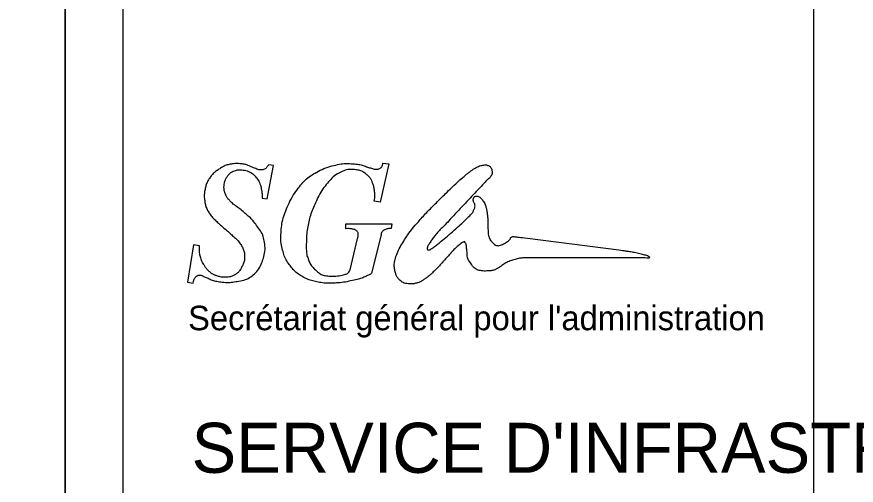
# Model space of a CAD drawing. Extents: x -21 to 21, y -29.7 to 0.
# Drawn here: x -0.42 to 6.85, y -12.39 to -8.34 of the extents above; entities that cross this region are included whole.
import ezdxf

# ---------------------------------------------------------------- set-up
doc = ezdxf.new("R2010")
doc.units = 0
doc.layers.add('Cartouches-Titres', color=7, linetype='Continuous')

msp = doc.modelspace()

# ---------------------------------------------------------------- linework, layer by layer
at = {"layer": 'Cartouches-Titres'}
for p, q in [((-0.0001, 0), (0, -29.7)), ((0, -29.7), (-0.0001, 0)), ((2.7347, -10.2257), (2.6519, -10.5569)), ((2.4658, -10.5273), (2.5308, -10.2578)), ((3.4574, -10.2822), (3.4561, -10.2822)), ((4.0037, -10.254), (4.7948, -10.3557)), ((4.7948, -10.4245), (4.0037, -10.4243))]:
    msp.add_line(p, q, dxfattribs=at)
for points in [[(-20.9999, -29.7), (0, -29.7), (0, 0), (-20.9999, 0)], [(-0.0001, 0), (0, -29.7), (21, -29.7), (20.9999, 0)], [(0, -29.7), (20.9999, -29.7), (20.9999, 0), (0, 0)]]:
    msp.add_lwpolyline(points, close=True, dxfattribs=at)
for points in [[(1.6644, -14.6077), (0.4999, -14.6077), (0.4999, -0.5036), (6.4782, -0.5036), (6.4783, -14.6077), (5.3139, -14.6077)], [(1.7061, -9.9067), (1.7482, -9.9131), (1.8017, -9.6236), (1.7635, -9.6179)], [(2.75, -9.6057), (2.801, -9.6108), (2.7258, -9.9433), (2.6748, -9.933)], [(2.4288, -10.1718), (2.4301, -10.1294), (2.8265, -10.1294), (2.8226, -10.1705)], [(1.1625, -10.3194), (1.1109, -10.313), (1.0593, -10.6358), (1.1084, -10.6429)]]:
    msp.add_lwpolyline(points, dxfattribs=at)
for points in [[(1.1084, -10.6429), (1.1083, -10.6301), (1.1121, -10.6154), (1.1186, -10.6044), (1.1251, -10.5932), (1.1361, -10.5816), (1.1473, -10.5761), (1.1556, -10.572), (1.1676, -10.5737), (1.1772, -10.5755), (1.1857, -10.5771), (1.1932, -10.5832), (1.2014, -10.5864), (1.2371, -10.6001), (1.2719, -10.6197), (1.3091, -10.6262), (1.359, -10.6349), (1.4129, -10.6395), (1.4627, -10.632), (1.5155, -10.6239), (1.5761, -10.6109), (1.6169, -10.5793), (1.6589, -10.5469), (1.6945, -10.4914), (1.7112, -10.44), (1.7287, -10.3864), (1.7318, -10.3192), (1.7195, -10.2642), (1.7082, -10.2133), (1.6726, -10.1652), (1.6405, -10.1223), (1.6127, -10.0852), (1.5748, -10.0552), (1.5398, -10.0241), (1.5045, -9.9928), (1.4626, -9.9682), (1.4296, -9.9349), (1.4109, -9.9162), (1.3937, -9.8927), (1.385, -9.8682), (1.3761, -9.8435), (1.3728, -9.8132), (1.3767, -9.7873), (1.3806, -9.7613), (1.3927, -9.733), (1.4085, -9.7122), (1.4222, -9.6943), (1.4441, -9.6788), (1.4653, -9.6711), (1.4885, -9.6627), (1.5169, -9.6613), (1.5417, -9.6641), (1.5642, -9.6666), (1.5874, -9.6761), (1.6074, -9.6872), (1.6235, -9.6962), (1.6382, -9.71), (1.6501, -9.7244), (1.6641, -9.7414), (1.6773, -9.7609), (1.6851, -9.7815), (1.6949, -9.8073), (1.6983, -9.8361), (1.703, -9.8637), (1.7053, -9.8778), (1.7064, -9.8924), (1.7061, -9.9067)], [(1.7635, -9.6179), (1.7598, -9.6216), (1.7562, -9.6255), (1.7527, -9.6294), (1.7455, -9.6375), (1.7407, -9.6494), (1.7316, -9.6538), (1.7184, -9.6603), (1.7008, -9.6635), (1.6857, -9.6622), (1.6672, -9.6605), (1.649, -9.6512), (1.6309, -9.6448), (1.604, -9.6353), (1.5785, -9.6188), (1.5506, -9.6147), (1.5109, -9.6087), (1.4675, -9.607), (1.4283, -9.6147), (1.394, -9.6213), (1.3596, -9.6383), (1.3302, -9.6577), (1.3014, -9.6766), (1.2737, -9.7016), (1.2537, -9.7295), (1.2344, -9.7564), (1.2193, -9.7896), (1.2123, -9.822), (1.2042, -9.8589), (1.2025, -9.9002), (1.2084, -9.9375), (1.2138, -9.9715), (1.2277, -10.0066), (1.246, -10.0357), (1.2668, -10.0686), (1.2974, -10.0961), (1.3257, -10.1236), (1.3601, -10.1571), (1.3994, -10.1854), (1.434, -10.2186), (1.4646, -10.2479), (1.4992, -10.276), (1.5213, -10.311), (1.5387, -10.3385), (1.5512, -10.374), (1.5526, -10.406), (1.5539, -10.4371), (1.5434, -10.4721), (1.5296, -10.5004), (1.5171, -10.526), (1.4966, -10.552), (1.4735, -10.5678), (1.452, -10.5824), (1.4222, -10.5899), (1.3958, -10.5915), (1.3663, -10.5933), (1.334, -10.5878), (1.3059, -10.578), (1.2828, -10.57), (1.2606, -10.5548), (1.2422, -10.5382), (1.2247, -10.5224), (1.2107, -10.5015), (1.1982, -10.4811), (1.1876, -10.4638), (1.1789, -10.4446), (1.1727, -10.4253), (1.167, -10.4074), (1.1644, -10.3882), (1.1625, -10.3694), (1.161, -10.3529), (1.161, -10.3359), (1.1625, -10.3194)], [(2.6519, -10.5569), (2.6476, -10.5623), (2.6416, -10.5669), (2.6353, -10.5697), (2.6013, -10.5845), (2.5668, -10.6005), (2.5308, -10.6095), (2.4712, -10.6244), (2.4097, -10.6372), (2.3485, -10.6416), (2.2954, -10.6454), (2.2401, -10.6435), (2.1879, -10.6339), (2.1428, -10.6255), (2.0963, -10.6103), (2.0566, -10.5877), (2.0182, -10.5658), (1.9809, -10.5351), (1.9534, -10.5004), (1.924, -10.4632), (1.8984, -10.4178), (1.8859, -10.372), (1.8703, -10.3151), (1.8646, -10.2515), (1.8693, -10.1923), (1.8744, -10.1282), (1.8904, -10.0618), (1.9152, -10.0023), (1.944, -9.933), (1.9835, -9.8645), (2.0299, -9.8059), (2.0655, -9.761), (2.1116, -9.72), (2.1612, -9.6917), (2.2217, -9.6571), (2.2917, -9.6314), (2.36, -9.6172), (2.4154, -9.6057), (2.4756, -9.6088), (2.532, -9.6147), (2.5707, -9.6187), (2.6076, -9.6365), (2.6455, -9.6468), (2.6598, -9.6506), (2.6744, -9.6568), (2.6888, -9.657), (2.7016, -9.6572), (2.716, -9.6539), (2.7271, -9.648), (2.7347, -9.644), (2.7407, -9.6352), (2.7449, -9.6275), (2.7483, -9.6211), (2.7503, -9.6129), (2.75, -9.6057)], [(2.6748, -9.933), (2.68, -9.9124), (2.6818, -9.89), (2.6799, -9.8688), (2.6771, -9.8374), (2.6721, -9.8043), (2.6608, -9.7751), (2.6517, -9.7517), (2.6377, -9.7268), (2.6187, -9.7109), (2.5931, -9.6895), (2.5596, -9.6681), (2.5269, -9.6634), (2.4844, -9.6574), (2.4321, -9.6604), (2.3931, -9.6788), (2.3433, -9.7024), (2.2966, -9.7454), (2.2606, -9.7892), (2.2188, -9.84), (2.1877, -9.9021), (2.1599, -9.9625), (2.1359, -10.0147), (2.1169, -10.0707), (2.1051, -10.1268), (2.0927, -10.1854), (2.0877, -10.2467), (2.0872, -10.3065), (2.0869, -10.3485), (2.0888, -10.3937), (2.1025, -10.4323), (2.1151, -10.4677), (2.1391, -10.5031), (2.1663, -10.5286), (2.1909, -10.5518), (2.2249, -10.5737), (2.258, -10.5787), (2.3107, -10.5866), (2.3723, -10.5798), (2.4237, -10.5671), (2.4416, -10.5627), (2.4603, -10.545), (2.4658, -10.5273)], [(3.4561, -10.2822), (3.4301, -10.2971), (3.4053, -10.3155), (3.3834, -10.3361), (3.3484, -10.369), (3.3182, -10.4073), (3.2853, -10.4426), (3.2545, -10.4757), (3.2248, -10.5102), (3.1923, -10.5415), (3.1687, -10.5641), (3.144, -10.5863), (3.1171, -10.6044), (3.0935, -10.6201), (3.0676, -10.6358), (3.0406, -10.6429), (3.0136, -10.6499), (2.9825, -10.651), (2.9552, -10.6467), (2.9362, -10.6437), (2.9155, -10.6342), (2.9017, -10.621), (2.8836, -10.6038), (2.8658, -10.5799), (2.8596, -10.5556), (2.8505, -10.52), (2.8466, -10.4773), (2.8558, -10.4413), (2.87, -10.3857), (2.8994, -10.3309), (2.9297, -10.2809), (2.9648, -10.2231), (3.0073, -10.1687), (3.0521, -10.1179), (3.1296, -10.0297), (3.2135, -9.9467), (3.2968, -9.8637), (3.344, -9.8166), (3.3936, -9.772), (3.4433, -9.7276), (3.4642, -9.7091), (3.4858, -9.6913), (3.5084, -9.675), (3.5279, -9.6609), (3.5479, -9.6463), (3.5695, -9.6365), (3.5874, -9.6284), (3.6076, -9.6232), (3.6269, -9.6211), (3.6394, -9.6197), (3.6539, -9.6213), (3.6651, -9.6262), (3.6743, -9.6303), (3.6831, -9.6392), (3.6881, -9.648), (3.6933, -9.6572), (3.6953, -9.6694), (3.6957, -9.6801), (3.6961, -9.6899), (3.6959, -9.7016), (3.6906, -9.7097), (3.6776, -9.7294), (3.6576, -9.7457), (3.6409, -9.7636), (3.5867, -9.8215), (3.5321, -9.879), (3.4778, -9.9369), (3.4199, -9.9984), (3.3623, -10.0601), (3.3044, -10.1217), (3.2726, -10.1556), (3.2385, -10.1875), (3.2088, -10.2231), (3.185, -10.2517), (3.164, -10.2831), (3.1438, -10.3143), (3.1394, -10.3211), (3.1365, -10.3294), (3.1349, -10.3374), (3.1339, -10.3423), (3.1336, -10.3497), (3.1362, -10.3528), (3.1383, -10.3553), (3.1447, -10.3538), (3.1489, -10.354), (3.1523, -10.3542), (3.1564, -10.3559), (3.1591, -10.354), (3.1903, -10.3328), (3.2214, -10.3092), (3.2509, -10.2847), (3.3102, -10.2356), (3.3686, -10.1852), (3.4255, -10.1333), (3.4604, -10.1014), (3.4948, -10.068), (3.5262, -10.0331), (3.5321, -10.0265), (3.5347, -10.0172), (3.5377, -10.0087), (3.5419, -9.9967), (3.5485, -9.9838), (3.5479, -9.9715), (3.5472, -9.9577), (3.5367, -9.9444), (3.5338, -9.9304), (3.5324, -9.9234), (3.5323, -9.9148), (3.5351, -9.9086), (3.5379, -9.9024), (3.5441, -9.8957), (3.5504, -9.8932), (3.5582, -9.8901), (3.5697, -9.8883), (3.5772, -9.8919), (3.5901, -9.8982), (3.6022, -9.9108), (3.6116, -9.9227), (3.6226, -9.9369), (3.6328, -9.9531), (3.6384, -9.9702), (3.6477, -9.9993), (3.6529, -10.0307), (3.6562, -10.0614), (3.6602, -10.0987), (3.6574, -10.1368), (3.66, -10.1743), (3.6616, -10.1967), (3.6621, -10.2202), (3.6689, -10.2411), (3.6748, -10.2591), (3.6854, -10.2775), (3.6983, -10.2911), (3.7096, -10.3032), (3.7261, -10.316), (3.7416, -10.3181), (3.758, -10.3203), (3.7777, -10.3115), (3.7938, -10.304), (3.8125, -10.2953), (3.8305, -10.2827), (3.8461, -10.2693), (3.8534, -10.263), (3.8552, -10.2498), (3.8627, -10.2449), (3.8696, -10.2404), (3.8805, -10.2401), (3.8894, -10.2411), (3.9275, -10.2451), (3.9656, -10.2494), (4.0037, -10.254)], [(2.5308, -10.2578), (2.5368, -10.2437), (2.5384, -10.2226), (2.5346, -10.2077), (2.532, -10.1978), (2.521, -10.1886), (2.5117, -10.1833), (2.5006, -10.177), (2.4864, -10.1749), (2.4734, -10.173), (2.4588, -10.171), (2.4435, -10.1706), (2.4288, -10.1718)], [(2.8226, -10.1705), (2.8109, -10.1694), (2.7982, -10.1708), (2.787, -10.1743), (2.7727, -10.1789), (2.7563, -10.1849), (2.7462, -10.1949), (2.7389, -10.202), (2.7339, -10.2155), (2.7347, -10.2257)], [(4.0037, -10.4243), (3.9872, -10.4245), (3.9708, -10.425), (3.9544, -10.4259), (3.9342, -10.4271), (3.9141, -10.4321), (3.8945, -10.4375), (3.8737, -10.4432), (3.8529, -10.4502), (3.8334, -10.4593), (3.8143, -10.4682), (3.7965, -10.4801), (3.7786, -10.4914), (3.7672, -10.4985), (3.757, -10.5077), (3.7454, -10.5145), (3.7353, -10.5205), (3.7247, -10.5265), (3.7136, -10.5299), (3.7005, -10.5338), (3.6865, -10.5355), (3.6728, -10.5363), (3.6499, -10.5377), (3.6263, -10.5398), (3.6039, -10.5363), (3.5855, -10.5334), (3.5654, -10.5278), (3.5504, -10.5171), (3.5331, -10.5047), (3.5195, -10.4851), (3.5071, -10.467), (3.4974, -10.453), (3.4885, -10.4372), (3.4841, -10.4208), (3.4783, -10.3987), (3.4793, -10.3746), (3.4765, -10.3515), (3.4746, -10.336), (3.4742, -10.32), (3.4701, -10.3053), (3.4678, -10.2969), (3.4632, -10.2885), (3.4574, -10.2822)], [(4.7948, -10.3557), (4.821, -10.3594), (4.8472, -10.3631), (4.8734, -10.3669), (4.9189, -10.3735), (4.964, -10.3838), (5.0085, -10.3951), (5.0248, -10.3992), (5.0431, -10.4049), (5.0557, -10.4131), (5.0588, -10.4152), (5.0572, -10.4233), (5.0557, -10.4259), (5.0547, -10.4275), (5.0506, -10.426), (5.048, -10.4259), (5.0174, -10.4255), (4.9868, -10.4247), (4.9562, -10.4246), (4.9024, -10.4245), (4.8486, -10.4245), (4.7948, -10.4245)]]:
    msp.add_open_spline(points, degree=3, dxfattribs=at)

# ---------------------------------------------------------------- texts
for s, height, p in [("Secrétariat général pour l'administration", 0.211703, (1.0633, -11.0507)), ("SERVICE D'INFRASTRUCTURE", 0.433173, (1.0938, -12.2848))]:
    msp.add_text(s, height=height, rotation=360, dxfattribs=at).set_placement(p)

doc.saveas('drawing.dxf')
